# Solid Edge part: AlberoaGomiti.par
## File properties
Author: Luca
Template: Normal.par
Last saved by: Luca
Revision: 14
Application: Solid Edge
Densità: 0.0000078 kg/mm^3
Precisione: 0.010
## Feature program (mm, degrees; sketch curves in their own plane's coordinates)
sketch for "unnamed Protrusion 1" plane through (0, 0, 0) normal (0, 0, 1) x-axis (1, 0, 0)
  circle centre (0, 0) radius 25
extrude "unnamed Protrusion 1" add finite 15 along +normal
sketch for "ExtrudedProtrusion_2" plane through (0, 0, 0) normal (0, 0, -1) x-axis (0, 1, 0)
  line (-32, -1.6726) -> (-15.266, 32.48)
  arc centre (0, 25) radius 17 from (-15.266, 32.48) to (15.266, 32.48) cw
  line (32, -1.6726) -> (15.266, 32.48)
  line (32, -1.6726) -> (32, -34.4238)
  arc centre (0, 0) radius 47 from (32, -34.4238) to (-32, -34.4238) cw
  line (-32, -1.6726) -> (-32, -34.4238)
  dimension (linear) = 32
extrude "ExtrudedProtrusion_2" add finite 10 along +normal
sketch for "ExtrudedProtrusion_7" plane through (-2.5, 0, -10) normal (0, 0, -1) x-axis (1, 0, 0)
  circle centre (27.5, 0) radius 15
extrude "ExtrudedProtrusion_7" add finite 6 along +normal
sketch for "ExtrudedCutout_1" #1 plane through (-2.5, 0, -10) normal (0, 0, -1) x-axis (1, 0, 0)
  circle centre (27.5, 0) radius 47.5
sketch for "ExtrudedCutout_1" #2 plane through (-2.5, 0, -10) normal (0, 0, -1) x-axis (1, 0, 0)
  circle centre (27.5, 0) radius 17
extrude "ExtrudedCutout_1" cut finite 2 along -normal
sketch for "ExtrudedCutout_2" plane through (-2.5, 0, 0) normal (0, 0, 1) x-axis (0.897998, -0.44, 0)
  line (2.245, 29.1) -> (24.6949, 29.1)
  arc centre (24.6949, 12.1) radius 17 from (24.6949, 29.1) to (38.129, 1.6824) cw
  line (24.3717, -16.0584) -> (38.129, 1.6824)
  arc centre (2.245, 1.1) radius 28 from (2.245, 29.1) to (24.3717, -16.0584) cw
extrude "ExtrudedCutout_2" cut finite 5 along -normal
draft "Draft_1"  Angles1 = 65 deg
sketch for "unnamed Cutout 1" #1 plane through (-8.8325, 0, 0) normal (0, 0, 1) x-axis (-0.897998, -0.44, 0)
  circle centre (28.4629, 10.5527) radius 6
sketch for "unnamed Cutout 1" #2 plane through (-8.8325, 0, 0) normal (0, 0, 1) x-axis (-0.897998, -0.44, 0)
  circle centre (9.1029, -28.9592) radius 6
extrude "unnamed Cutout 1" cut through along -normal
mirror "unnamed Mirror 1" of "unnamed Protrusion 1", "ExtrudedProtrusion_2", "ExtrudedProtrusion_7", "ExtrudedCutout_1", "ExtrudedCutout_2", "Draft_1", "unnamed Cutout 1" about plane through (0, 0, -16) normal (0, 0, 1)
extrude "unnamed Protrusion 2" add finite 15
extrude "unnamed Protrusion 3" add finite 10
extrude "unnamed Protrusion 4" add finite 6
extrude "unnamed Cutout 2" cut finite 2
extrude "unnamed Cutout 3" cut finite 5
draft "unnamed Draft 1"
extrude "unnamed Cutout 4" cut through
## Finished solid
Body 1: solid body, 35 faces, 76 edges, 40 vertices.
  Faces by surface: plane 20, cylinder 13, cone 2
  Edges by curve: line 36, circle 32, intersection 8
Bounding box of the edges (mm): 89.000 x 64.000 x 62.000, from (-47, -32, -47) to (42, 32, 15).
Cylindrical faces by radius (mm): R6 x4, R15 x1, R17 x2, R25 x2, R47 x2, R47.5 x2
Conical faces (half-angle, radius in mm at the cone's reference point): 65 deg R28 x2
Planar faces by outward normal: +y 2, +z 6, -y 2, -z 6, oblique 4
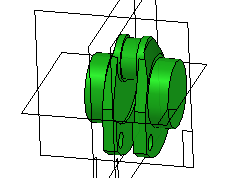
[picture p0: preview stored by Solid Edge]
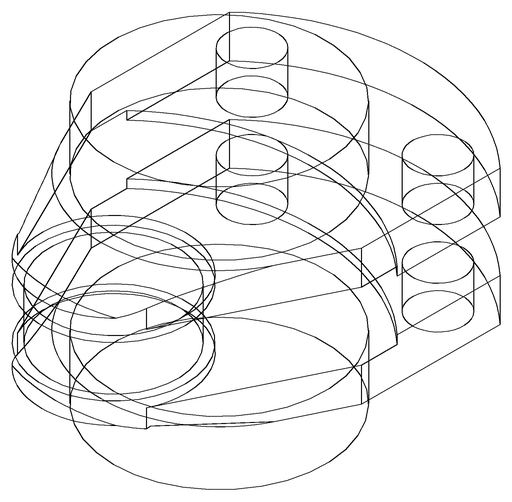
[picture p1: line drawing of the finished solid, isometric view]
